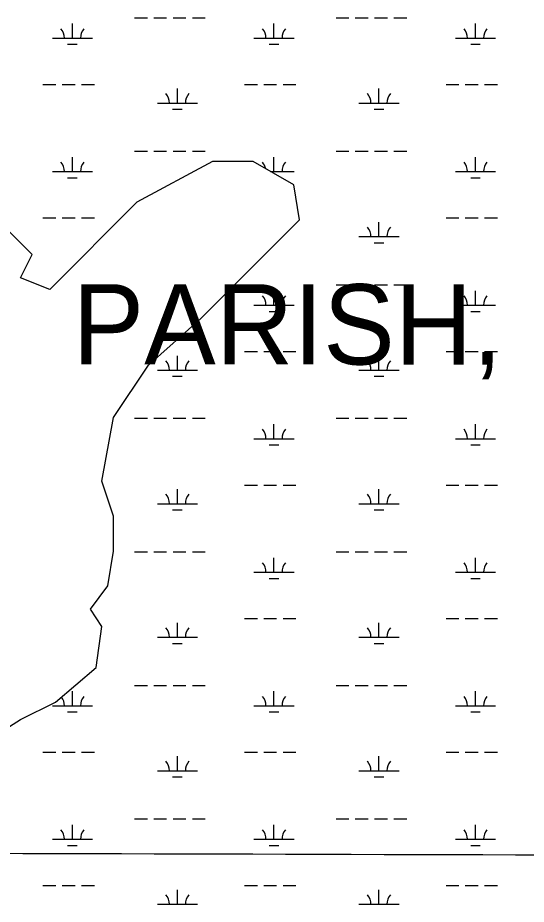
# Model space of a CAD drawing. Extents: x 3177185 to 3215018, y 812988 to 838321.
# Drawn here: x 3184301 to 3185567, y 824327 to 826535 of the extents above; entities that cross this region are included whole.
import ezdxf

# ---------------------------------------------------------------- set-up
doc = ezdxf.new("R2010")
doc.units = 0
for name, color, linetype in [('V-GRID-MAJR', 7, 'Continuous'), ('V-TOPO-GNAM-IDEN', 7, 'Continuous'), ('V-WETL-SWMP', 7, 'Continuous')]:
    doc.layers.add(name, color=color, linetype=linetype)

msp = doc.modelspace()

# ---------------------------------------------------------------- linework, layer by layer
at = {"layer": 'V-GRID-MAJR'}
msp.add_spline([(3181368.912, 824461.486), (3186603.869, 824447.399), (3191838.828, 824434.0750000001), (3197073.789, 824421.511), (3202308.752, 824409.709), (3207543.717, 824398.669), (3212778.683, 824388.39), (3212778.684, 824388.39)], degree=3, dxfattribs=at)
at = {"layer": 'V-WETL-SWMP'}
for p, q in [((3184591.5927016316, 826535.3500609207), (3184623.5927016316, 826535.3500609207)), ((3184639.5927016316, 826535.3500609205), (3184671.5927016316, 826535.3500609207)), ((3184687.5927016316, 826535.3500609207), (3184719.5927016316, 826535.3500609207)), ((3184735.5927016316, 826535.3500609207), (3184767.5927016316, 826535.3500609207)), ((3185093.5007016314, 826535.3500609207), (3185125.5007016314, 826535.3500609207)), ((3185141.5007016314, 826535.3500609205), (3185173.5007016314, 826535.3500609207)), ((3185189.5007016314, 826535.3500609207), (3185221.5007016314, 826535.3500609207)), ((3185237.5007016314, 826535.3500609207), (3185269.5007016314, 826535.3500609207)), ((3184437.0007016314, 826484.6080609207), (3184437.0007016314, 826520.6080609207)), ((3184938.9087016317, 826484.6080609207), (3184938.9087016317, 826520.6080609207)), ((3185440.8167016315, 826484.6080609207), (3185440.8167016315, 826520.6080609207)), ((3184387.0007016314, 826484.6080609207), (3184487.000701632, 826484.6080609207)), ((3184888.9087016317, 826484.6080609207), (3184988.908701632, 826484.6080609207)), ((3185390.8167016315, 826484.6080609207), (3185490.816701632, 826484.6080609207)), ((3184425.0007016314, 826469.1770609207), (3184449.0007016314, 826469.177060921)), ((3184926.9087016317, 826469.1770609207), (3184950.9087016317, 826469.177060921)), ((3185428.8167016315, 826469.1770609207), (3185452.8167016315, 826469.177060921)), ((3184363.5927016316, 826369.1760609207), (3184395.592701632, 826369.1760609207)), ((3184411.5927016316, 826369.1760609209), (3184443.5927016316, 826369.1760609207)), ((3184459.5927016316, 826369.1760609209), (3184491.5927016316, 826369.1760609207)), ((3184865.5007016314, 826369.1760609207), (3184897.500701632, 826369.1760609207)), ((3184913.5007016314, 826369.1760609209), (3184945.5007016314, 826369.1760609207)), ((3184961.5007016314, 826369.1760609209), (3184993.5007016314, 826369.1760609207)), ((3185367.4087016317, 826369.1760609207), (3185399.408701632, 826369.1760609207)), ((3185415.4087016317, 826369.1760609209), (3185447.4087016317, 826369.1760609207)), ((3185463.4087016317, 826369.1760609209), (3185495.4087016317, 826369.1760609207)), ((3184698.4367016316, 826322.7460609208), (3184698.4367016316, 826358.746060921)), ((3185200.3447016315, 826322.7460609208), (3185200.3447016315, 826358.746060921)), ((3184648.436701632, 826322.7460609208), (3184748.4367016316, 826322.7460609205)), ((3184686.4367016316, 826307.3150609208), (3184710.4367016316, 826307.315060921)), ((3185150.344701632, 826322.7460609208), (3185250.3447016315, 826322.7460609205)), ((3185188.3447016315, 826307.3150609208), (3185212.3447016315, 826307.315060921)), ((3184591.5927016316, 826202.6750609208), (3184623.5927016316, 826202.6750609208)), ((3184639.5927016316, 826202.6750609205), (3184671.5927016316, 826202.6750609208)), ((3184687.5927016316, 826202.6750609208), (3184719.5927016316, 826202.6750609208)), ((3184735.5927016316, 826202.6750609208), (3184767.5927016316, 826202.6750609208)), ((3185093.5007016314, 826202.6750609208), (3185125.5007016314, 826202.6750609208)), ((3185141.5007016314, 826202.6750609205), (3185173.5007016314, 826202.6750609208)), ((3185189.5007016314, 826202.6750609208), (3185221.5007016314, 826202.6750609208)), ((3185237.5007016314, 826202.6750609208), (3185269.5007016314, 826202.6750609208)), ((3184437.0007016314, 826151.9330609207), (3184437.0007016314, 826187.9330609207)), ((3184785.522, 826176.9879999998), (3184597.404, 826075.6059999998)), ((3184886.816, 826176.9879999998), (3184785.522, 826176.9879999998)), ((3184988.11, 826119.056), (3184886.816, 826176.9879999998)), ((3184938.9087016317, 826151.9330609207), (3184938.9087016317, 826187.9330609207)), ((3185440.8167016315, 826151.9330609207), (3185440.8167016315, 826187.9330609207)), ((3184387.0007016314, 826151.9330609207), (3184487.000701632, 826151.9330609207)), ((3184930.624516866, 826151.9330609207), (3184988.908701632, 826151.9330609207)), ((3185390.8167016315, 826151.9330609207), (3185490.816701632, 826151.9330609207)), ((3184425.0007016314, 826136.5020609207), (3184449.0007016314, 826136.5020609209)), ((3185428.8167016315, 826136.5020609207), (3185452.8167016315, 826136.5020609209)), ((3185002.58, 826032.1569999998), (3184988.11, 826119.056)), ((3184597.404, 826075.606), (3184380.345, 825858.3599999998)), ((3184336.934, 825945.2589999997), (3184264.5810000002, 826017.6739999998)), ((3184363.5927016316, 826036.5010609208), (3184395.592701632, 826036.5010609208)), ((3184411.5927016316, 826036.501060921), (3184443.5927016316, 826036.5010609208)), ((3184459.5927016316, 826036.501060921), (3184491.5927016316, 826036.5010609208)), ((3184756.58, 825785.9449999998), (3185002.58, 826032.1569999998)), ((3185200.3447016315, 825990.0710609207), (3185200.3447016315, 826026.071060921)), ((3185367.4087016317, 826036.5010609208), (3185399.408701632, 826036.5010609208)), ((3185415.4087016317, 826036.501060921), (3185447.4087016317, 826036.5010609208)), ((3185463.4087016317, 826036.501060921), (3185495.4087016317, 826036.5010609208)), ((3185150.344701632, 825990.0710609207), (3185250.3447016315, 825990.0710609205)), ((3185188.3447016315, 825974.6400609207), (3185212.3447016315, 825974.640060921)), ((3184307.9930000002, 825887.326), (3184336.934, 825945.2589999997)), ((3184380.345, 825858.3599999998), (3184307.9930000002, 825887.326)), ((3185093.5007016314, 825870.0000609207), (3185125.5007016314, 825870.0000609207)), ((3185141.5007016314, 825870.0000609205), (3185173.5007016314, 825870.0000609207)), ((3185189.5007016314, 825870.0000609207), (3185221.5007016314, 825870.0000609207)), ((3185237.5007016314, 825870.0000609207), (3185269.5007016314, 825870.0000609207)), ((3184938.9087016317, 825819.2580609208), (3184938.9087016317, 825855.2580609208)), ((3185440.8167016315, 825819.2580609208), (3185440.8167016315, 825855.2580609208)), ((3184888.9087016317, 825819.2580609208), (3184988.908701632, 825819.2580609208)), ((3185390.8167016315, 825819.2580609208), (3185490.816701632, 825819.2580609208)), ((3184926.9087016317, 825803.8270609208), (3184950.9087016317, 825803.827060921)), ((3185428.8167016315, 825803.8270609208), (3185452.8167016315, 825803.827060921)), ((3184626.345, 825670.0800000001), (3184756.58, 825785.9449999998)), ((3184698.4367016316, 825657.3960609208), (3184698.4367016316, 825693.396060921)), ((3184865.5007016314, 825703.8260609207), (3184897.500701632, 825703.8260609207)), ((3184913.5007016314, 825703.826060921), (3184945.5007016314, 825703.8260609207)), ((3184961.5007016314, 825703.826060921), (3184993.5007016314, 825703.8260609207)), ((3185200.3447016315, 825657.3960609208), (3185200.3447016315, 825693.396060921)), ((3185367.4087016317, 825703.8260609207), (3185399.408701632, 825703.8260609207)), ((3185415.4087016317, 825703.826060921), (3185447.4087016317, 825703.8260609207)), ((3185463.4087016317, 825703.826060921), (3185495.4087016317, 825703.8260609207)), ((3184539.522, 825539.733), (3184626.345, 825670.0800000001)), ((3184648.436701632, 825657.3960609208), (3184748.4367016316, 825657.3960609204)), ((3184686.4367016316, 825641.9650609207), (3184710.4367016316, 825641.9650609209)), ((3185150.344701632, 825657.3960609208), (3185250.3447016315, 825657.3960609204)), ((3185188.3447016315, 825641.9650609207), (3185212.3447016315, 825641.9650609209)), ((3184510.5810000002, 825380.419), (3184539.522, 825539.733)), ((3184591.5927016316, 825537.3250609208), (3184623.5927016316, 825537.3250609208)), ((3184639.5927016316, 825537.3250609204), (3184671.5927016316, 825537.3250609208)), ((3184687.5927016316, 825537.3250609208), (3184719.5927016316, 825537.3250609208)), ((3184735.5927016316, 825537.3250609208), (3184767.5927016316, 825537.3250609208)), ((3185093.5007016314, 825537.3250609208), (3185125.5007016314, 825537.3250609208)), ((3185141.5007016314, 825537.3250609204), (3185173.5007016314, 825537.3250609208)), ((3185189.5007016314, 825537.3250609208), (3185221.5007016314, 825537.3250609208)), ((3185237.5007016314, 825537.3250609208), (3185269.5007016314, 825537.3250609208)), ((3184938.9087016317, 825486.5830609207), (3184938.9087016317, 825522.5830609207)), ((3185440.8167016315, 825486.5830609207), (3185440.8167016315, 825522.5830609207)), ((3184888.9087016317, 825486.5830609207), (3184988.908701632, 825486.5830609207)), ((3185390.8167016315, 825486.5830609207), (3185490.816701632, 825486.5830609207)), ((3184926.9087016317, 825471.1520609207), (3184950.9087016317, 825471.152060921)), ((3185428.8167016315, 825471.1520609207), (3185452.8167016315, 825471.152060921)), ((3184539.522, 825293.5210000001), (3184510.5810000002, 825380.419)), ((3184698.4367016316, 825324.7210609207), (3184698.4367016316, 825360.721060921)), ((3184865.5007016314, 825371.1510609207), (3184897.500701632, 825371.1510609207)), ((3184913.5007016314, 825371.151060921), (3184945.5007016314, 825371.1510609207)), ((3184961.5007016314, 825371.151060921), (3184993.5007016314, 825371.1510609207)), ((3185200.3447016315, 825324.7210609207), (3185200.3447016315, 825360.721060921)), ((3185367.4087016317, 825371.1510609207), (3185399.408701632, 825371.1510609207)), ((3185415.4087016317, 825371.151060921), (3185447.4087016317, 825371.1510609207)), ((3185463.4087016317, 825371.151060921), (3185495.4087016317, 825371.1510609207)), ((3184648.436701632, 825324.7210609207), (3184748.4367016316, 825324.7210609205)), ((3184686.4367016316, 825309.2900609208), (3184710.4367016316, 825309.290060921)), ((3185150.344701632, 825324.7210609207), (3185250.3447016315, 825324.7210609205)), ((3185188.3447016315, 825309.2900609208), (3185212.3447016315, 825309.290060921)), ((3184539.522, 825206.622), (3184539.522, 825293.5210000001)), ((3184525.051, 825119.724), (3184539.522, 825206.622)), ((3184591.5927016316, 825204.6500609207), (3184623.5927016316, 825204.6500609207)), ((3184639.5927016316, 825204.6500609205), (3184671.5927016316, 825204.6500609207)), ((3184687.5927016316, 825204.6500609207), (3184719.5927016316, 825204.6500609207)), ((3184735.5927016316, 825204.6500609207), (3184767.5927016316, 825204.6500609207)), ((3185093.5007016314, 825204.6500609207), (3185125.5007016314, 825204.6500609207)), ((3185141.5007016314, 825204.6500609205), (3185173.5007016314, 825204.6500609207)), ((3185189.5007016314, 825204.6500609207), (3185221.5007016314, 825204.6500609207)), ((3185237.5007016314, 825204.6500609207), (3185269.5007016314, 825204.6500609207)), ((3184938.9087016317, 825153.9080609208), (3184938.9087016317, 825189.9080609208)), ((3185440.8167016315, 825153.9080609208), (3185440.8167016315, 825189.9080609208)), ((3184888.9087016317, 825153.9080609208), (3184988.908701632, 825153.9080609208)), ((3185390.8167016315, 825153.9080609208), (3185490.816701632, 825153.9080609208)), ((3184926.9087016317, 825138.4770609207), (3184950.9087016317, 825138.477060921)), ((3185428.8167016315, 825138.4770609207), (3185452.8167016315, 825138.477060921)), ((3184481.64, 825061.792), (3184525.051, 825119.724)), ((3184510.5810000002, 825018.3419999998), (3184481.64, 825061.792)), ((3184698.4367016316, 824992.0460609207), (3184698.4367016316, 825028.0460609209)), ((3184865.5007016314, 825038.4760609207), (3184897.500701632, 825038.4760609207)), ((3184913.5007016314, 825038.476060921), (3184945.5007016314, 825038.4760609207)), ((3184961.5007016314, 825038.476060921), (3184993.5007016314, 825038.4760609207)), ((3185200.3447016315, 824992.0460609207), (3185200.3447016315, 825028.0460609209)), ((3185367.4087016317, 825038.4760609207), (3185399.408701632, 825038.4760609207)), ((3185415.4087016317, 825038.476060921), (3185447.4087016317, 825038.4760609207)), ((3185463.4087016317, 825038.476060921), (3185495.4087016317, 825038.4760609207)), ((3184496.11, 824916.961), (3184510.5810000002, 825018.3419999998)), ((3184648.436701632, 824992.0460609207), (3184748.4367016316, 824992.0460609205)), ((3184686.4367016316, 824976.6150609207), (3184710.4367016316, 824976.615060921)), ((3185150.344701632, 824992.0460609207), (3185250.3447016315, 824992.0460609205)), ((3185188.3447016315, 824976.6150609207), (3185212.3447016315, 824976.615060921)), ((3184394.816, 824830.062), (3184496.11, 824916.961)), ((3184591.5927016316, 824871.9750609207), (3184623.5927016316, 824871.9750609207)), ((3184639.5927016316, 824871.9750609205), (3184671.5927016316, 824871.9750609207)), ((3184687.5927016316, 824871.9750609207), (3184719.5927016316, 824871.9750609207)), ((3184735.5927016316, 824871.9750609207), (3184767.5927016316, 824871.9750609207)), ((3185093.5007016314, 824871.9750609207), (3185125.5007016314, 824871.9750609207)), ((3185141.5007016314, 824871.9750609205), (3185173.5007016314, 824871.9750609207)), ((3185189.5007016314, 824871.9750609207), (3185221.5007016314, 824871.9750609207)), ((3185237.5007016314, 824871.9750609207), (3185269.5007016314, 824871.9750609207)), ((3184437.0007016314, 824821.2330609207), (3184437.0007016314, 824857.2330609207)), ((3184938.9087016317, 824821.2330609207), (3184938.9087016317, 824857.2330609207)), ((3185440.8167016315, 824821.2330609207), (3185440.8167016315, 824857.2330609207)), ((3184307.9930000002, 824786.6129999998), (3184394.816, 824830.0619999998)), ((3184387.0007016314, 824821.2330609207), (3184487.000701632, 824821.2330609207)), ((3184425.0007016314, 824805.8020609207), (3184449.0007016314, 824805.802060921)), ((3184888.9087016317, 824821.2330609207), (3184988.908701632, 824821.2330609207)), ((3184926.9087016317, 824805.8020609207), (3184950.9087016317, 824805.802060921)), ((3185390.8167016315, 824821.2330609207), (3185490.816701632, 824821.2330609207)), ((3185428.8167016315, 824805.8020609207), (3185452.8167016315, 824805.802060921)), ((3184192.228, 824714.1979999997), (3184307.9930000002, 824786.6129999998)), ((3184363.5927016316, 824705.8010609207), (3184395.592701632, 824705.8010609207)), ((3184411.5927016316, 824705.8010609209), (3184443.5927016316, 824705.8010609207)), ((3184459.5927016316, 824705.8010609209), (3184491.5927016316, 824705.8010609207)), ((3184698.4367016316, 824659.3710609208), (3184698.4367016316, 824695.371060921)), ((3184865.5007016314, 824705.8010609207), (3184897.500701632, 824705.8010609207)), ((3184913.5007016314, 824705.8010609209), (3184945.5007016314, 824705.8010609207)), ((3184961.5007016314, 824705.8010609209), (3184993.5007016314, 824705.8010609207)), ((3185200.3447016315, 824659.3710609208), (3185200.3447016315, 824695.371060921)), ((3185367.4087016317, 824705.8010609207), (3185399.408701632, 824705.8010609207)), ((3185415.4087016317, 824705.8010609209), (3185447.4087016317, 824705.8010609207)), ((3185463.4087016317, 824705.8010609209), (3185495.4087016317, 824705.8010609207)), ((3184648.436701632, 824659.3710609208), (3184748.4367016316, 824659.3710609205)), ((3185150.344701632, 824659.3710609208), (3185250.3447016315, 824659.3710609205)), ((3184686.4367016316, 824643.9400609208), (3184710.4367016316, 824643.940060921)), ((3185188.3447016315, 824643.9400609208), (3185212.3447016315, 824643.940060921)), ((3184591.5927016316, 824539.3000609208), (3184623.5927016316, 824539.3000609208)), ((3184639.5927016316, 824539.3000609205), (3184671.5927016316, 824539.3000609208)), ((3184687.5927016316, 824539.3000609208), (3184719.5927016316, 824539.3000609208)), ((3184735.5927016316, 824539.3000609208), (3184767.5927016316, 824539.3000609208)), ((3185093.5007016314, 824539.3000609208), (3185125.5007016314, 824539.3000609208)), ((3185141.5007016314, 824539.3000609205), (3185173.5007016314, 824539.3000609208)), ((3185189.5007016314, 824539.3000609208), (3185221.5007016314, 824539.3000609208)), ((3185237.5007016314, 824539.3000609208), (3185269.5007016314, 824539.3000609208)), ((3184437.0007016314, 824488.5580609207), (3184437.0007016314, 824524.5580609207)), ((3184938.9087016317, 824488.5580609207), (3184938.9087016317, 824524.5580609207)), ((3185440.8167016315, 824488.5580609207), (3185440.8167016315, 824524.5580609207)), ((3184387.0007016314, 824488.5580609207), (3184487.000701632, 824488.5580609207)), ((3184425.0007016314, 824473.1270609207), (3184449.0007016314, 824473.1270609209)), ((3184888.9087016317, 824488.5580609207), (3184988.908701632, 824488.5580609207)), ((3184926.9087016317, 824473.1270609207), (3184950.9087016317, 824473.1270609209)), ((3185390.8167016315, 824488.5580609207), (3185490.816701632, 824488.5580609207)), ((3185428.8167016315, 824473.1270609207), (3185452.8167016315, 824473.1270609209)), ((3184363.5927016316, 824373.1260609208), (3184395.592701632, 824373.1260609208)), ((3184411.5927016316, 824373.126060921), (3184443.5927016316, 824373.1260609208)), ((3184459.5927016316, 824373.126060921), (3184491.5927016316, 824373.1260609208)), ((3184698.4367016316, 824326.6960609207), (3184698.4367016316, 824362.696060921)), ((3184865.5007016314, 824373.1260609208), (3184897.500701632, 824373.1260609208)), ((3184913.5007016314, 824373.126060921), (3184945.5007016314, 824373.1260609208)), ((3184961.5007016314, 824373.126060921), (3184993.5007016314, 824373.1260609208)), ((3185200.3447016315, 824326.6960609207), (3185200.3447016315, 824362.696060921)), ((3185367.4087016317, 824373.1260609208), (3185399.408701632, 824373.1260609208)), ((3185415.4087016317, 824373.126060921), (3185447.4087016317, 824373.1260609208)), ((3185463.4087016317, 824373.126060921), (3185495.4087016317, 824373.1260609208)), ((3184648.436701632, 824326.6960609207), (3184748.4367016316, 824326.6960609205)), ((3185150.344701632, 824326.6960609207), (3185250.3447016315, 824326.6960609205))]:
    msp.add_line(p, q, dxfattribs=at)
for centre, radius, start, end in [((3184381.7577655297, 826485.0828641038), 35.24628790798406, 359.2281799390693, 40.771838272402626), ((3184492.2436377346, 826485.0828641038), 35.24628790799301, 139.2281769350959, 180.77183526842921), ((3184883.6657655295, 826485.0828641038), 35.24628790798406, 359.2281799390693, 40.771838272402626), ((3184994.1516377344, 826485.0828641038), 35.24628790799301, 139.2281769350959, 180.77183526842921), ((3185385.57376553, 826485.0828641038), 35.24628790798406, 359.2281799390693, 40.771838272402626), ((3185496.0596377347, 826485.0828641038), 35.24628790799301, 139.2281769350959, 180.77183526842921), ((3184643.193765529, 826323.2208641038), 35.24628790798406, 359.2281799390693, 40.771838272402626), ((3184753.679637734, 826323.2208641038), 35.24628790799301, 139.2281769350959, 180.77183526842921), ((3185145.101765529, 826323.2208641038), 35.24628790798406, 359.2281799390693, 40.771838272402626), ((3185255.587637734, 826323.2208641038), 35.24628790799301, 139.2281769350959, 180.77183526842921), ((3184381.7577655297, 826152.4078641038), 35.24628790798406, 359.2281799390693, 40.771838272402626), ((3184492.2436377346, 826152.4078641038), 35.24628790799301, 139.2281769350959, 180.77183526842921), ((3184883.6657655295, 826152.4078641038), 35.24628790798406, 10.75606448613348, 40.77183827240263), ((3184994.1516377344, 826152.4078641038), 35.24628790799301, 139.2281769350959, 180.77183526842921), ((3185385.57376553, 826152.4078641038), 35.24628790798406, 359.2281799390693, 40.771838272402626), ((3185496.0596377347, 826152.4078641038), 35.24628790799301, 139.2281769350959, 180.77183526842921), ((3185145.101765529, 825990.5458641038), 35.24628790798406, 359.2281799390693, 40.771838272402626), ((3185255.587637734, 825990.5458641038), 35.24628790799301, 139.2281769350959, 180.77183526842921), ((3184883.6657655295, 825819.7328641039), 35.24628790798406, 359.2281799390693, 40.771838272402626), ((3184994.1516377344, 825819.7328641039), 35.24628790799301, 139.2281769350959, 180.77183526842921), ((3185385.57376553, 825819.7328641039), 35.24628790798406, 359.2281799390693, 40.771838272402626), ((3185496.0596377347, 825819.7328641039), 35.24628790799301, 139.2281769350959, 180.77183526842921), ((3184643.193765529, 825657.8708641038), 35.24628790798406, 359.2281799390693, 40.771838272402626), ((3184753.679637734, 825657.8708641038), 35.24628790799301, 139.2281769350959, 180.77183526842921), ((3185145.101765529, 825657.8708641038), 35.24628790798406, 359.2281799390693, 40.771838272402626), ((3185255.587637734, 825657.8708641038), 35.24628790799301, 139.2281769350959, 180.77183526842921), ((3184883.6657655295, 825487.0578641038), 35.24628790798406, 359.2281799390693, 40.771838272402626), ((3184994.1516377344, 825487.0578641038), 35.24628790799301, 139.2281769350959, 180.77183526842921), ((3185385.57376553, 825487.0578641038), 35.24628790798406, 359.2281799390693, 40.771838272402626), ((3185496.0596377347, 825487.0578641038), 35.24628790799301, 139.2281769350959, 180.77183526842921), ((3184643.193765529, 825325.1958641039), 35.24628790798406, 359.2281799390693, 40.771838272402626), ((3184753.679637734, 825325.1958641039), 35.24628790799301, 139.2281769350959, 180.77183526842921), ((3185145.101765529, 825325.1958641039), 35.24628790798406, 359.2281799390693, 40.771838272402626), ((3185255.587637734, 825325.1958641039), 35.24628790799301, 139.2281769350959, 180.77183526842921), ((3184883.6657655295, 825154.3828641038), 35.24628790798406, 359.2281799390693, 40.771838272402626), ((3184994.1516377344, 825154.3828641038), 35.24628790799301, 139.2281769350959, 180.77183526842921), ((3185385.57376553, 825154.3828641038), 35.24628790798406, 359.2281799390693, 40.771838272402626), ((3185496.0596377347, 825154.3828641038), 35.24628790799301, 139.2281769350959, 180.77183526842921), ((3184643.193765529, 824992.5208641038), 35.24628790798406, 359.2281799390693, 40.771838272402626), ((3184753.679637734, 824992.5208641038), 35.24628790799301, 139.2281769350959, 180.77183526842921), ((3185145.101765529, 824992.5208641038), 35.24628790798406, 359.2281799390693, 40.771838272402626), ((3185255.587637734, 824992.5208641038), 35.24628790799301, 139.2281769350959, 180.77183526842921), ((3184492.2436377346, 824821.7078641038), 35.24628790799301, 139.2281769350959, 180.77183526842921), ((3184883.6657655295, 824821.7078641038), 35.24628790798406, 359.2281799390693, 40.771838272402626), ((3184994.1516377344, 824821.7078641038), 35.24628790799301, 139.2281769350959, 180.77183526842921), ((3185385.57376553, 824821.7078641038), 35.24628790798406, 359.2281799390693, 40.771838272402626), ((3185496.0596377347, 824821.7078641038), 35.24628790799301, 139.2281769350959, 180.77183526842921), ((3184381.7577655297, 824821.7078641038), 35.24628790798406, 359.2281799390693, 37.10944757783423), ((3184643.193765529, 824659.8458641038), 35.24628790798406, 359.2281799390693, 40.771838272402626), ((3184753.679637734, 824659.8458641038), 35.24628790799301, 139.2281769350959, 180.77183526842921), ((3185145.101765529, 824659.8458641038), 35.24628790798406, 359.2281799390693, 40.771838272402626), ((3185255.587637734, 824659.8458641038), 35.24628790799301, 139.2281769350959, 180.77183526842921), ((3184381.7577655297, 824489.0328641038), 35.24628790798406, 359.2281799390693, 40.771838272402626), ((3184492.2436377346, 824489.0328641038), 35.24628790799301, 139.2281769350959, 180.77183526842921), ((3184883.6657655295, 824489.0328641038), 35.24628790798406, 359.2281799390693, 40.771838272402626), ((3184994.1516377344, 824489.0328641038), 35.24628790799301, 139.2281769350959, 180.77183526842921), ((3185385.57376553, 824489.0328641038), 35.24628790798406, 359.2281799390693, 40.771838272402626), ((3185496.0596377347, 824489.0328641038), 35.24628790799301, 139.2281769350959, 180.77183526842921), ((3184643.193765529, 824327.1708641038), 35.24628790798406, 359.2281799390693, 40.771838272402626), ((3184753.679637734, 824327.1708641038), 35.24628790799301, 139.2281769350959, 180.77183526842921), ((3185145.101765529, 824327.1708641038), 35.24628790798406, 359.2281799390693, 40.771838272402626), ((3185255.587637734, 824327.1708641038), 35.24628790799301, 139.2281769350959, 180.77183526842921)]:
    msp.add_arc(centre, radius, start, end, dxfattribs=at)

# ---------------------------------------------------------------- texts
at = {"layer": 'V-TOPO-GNAM-IDEN'}
msp.add_text('PARISH,', height=199.9999980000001, rotation=359.990962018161, dxfattribs=at).set_placement((3184437.1764139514, 825671.5382542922))

doc.saveas('drawing.dxf')
